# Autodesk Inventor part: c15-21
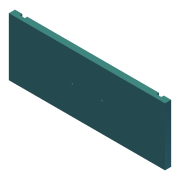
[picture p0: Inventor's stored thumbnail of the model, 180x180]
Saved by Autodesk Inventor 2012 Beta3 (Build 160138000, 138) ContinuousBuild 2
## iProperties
Created: 2011-02
Part Number: c15-21
Material: Default
Document SubType Name: Modeling
Designer: Beta-8540w
Density: 1 g/cm^3
Author: Beta-8540w
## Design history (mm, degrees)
sketch "Sketch1"
  geometry: L1 (-202.2, -75.2)-(202.2, -75.2); L2 (202.2, -75.2)-(202.2, 75.2); L3 (202.2, 75.2)-(-202.2, 75.2); L4 (-202.2, 75.2)-(-202.2, -75.2); 3 further points
  constraints: 8 end point, 2 midpoint, 2 parallel, 1 horizontal, 1 horizontal alignment, 1 perpendicular, 1 vertical alignment
  dimensions: "drawer_core_width" = 404.4 distance of L3.end L2.end (= drawer_width - 2 x edge_band_thickness); "drawer_core_height" = 150.4 distance of L2.end L1.end (= drawer_height - 2 x edge_band_thickness)
extrude "Drawer Face" new body sketch "Sketch1" distance "d2" = 15.875; taper "d3" = 0 deg
sketch "Sketch2"
  geometry: 1 further point
hole "Single Hole Pull" sketch "Sketch2" at (0, 0) diameter "d4" = 4.4958; stored, may be unused: countersink angle "d8" = 82 deg, drill point angle "d10" = 118 deg; dims "d5" = 19.05, "d6" = 8.4328, "d7" = 6.35, "d9" = 25.4
sketch "Sketch3"
  geometry: L1 (-38.1, 0)-(38.1, 0); 2 further points
  constraints: 2 end point, 1 coincident, 1 horizontal, 1 midpoint
  dimensions: "pull_width" = 76.2 distance of L1.start L1.end
hole "Double Hole Pull" sketch "Sketch3" at (-38.1, 0), (38.1, 0) diameter "d12" = 4.4958; stored, may be unused: countersink angle "d16" = 82 deg, drill point angle "d18" = 118 deg; dims "d13" = 19.05, "d14" = 8.4328, "d15" = 6.35, "d17" = 25.4
sketch "Sketch4"
  geometry: L1 (202.2, -75.2)-(-202.2, -75.2) reference; L2 (202.2, 75.2)-(202.2, -75.2) reference; L3 (-202.2, 75.2)-(202.2, 75.2) reference; L4 (-202.2, -75.2)-(-202.2, 75.2) reference; L5 (-183.15, 75.2)-(-170.45, 75.2); L6 (-170.45, 75.2)-(-170.45, -75.2); L7 (-170.45, -75.2)-(-183.15, -75.2); L8 (-183.15, -75.2)-(-183.15, 75.2); L9 (183.15, 75.2)-(170.45, 75.2); L10 (170.45, 75.2)-(170.45, -75.2); L11 (170.45, -75.2)-(183.15, -75.2); L12 (183.15, -75.2)-(183.15, 75.2); 1 further point
  constraints: 16 end point, 4 parallel, 4 point on line, 2 horizontal, 2 perpendicular, 1 collinear
  dimensions: "d19" = 12.7 distance of L5.start L5.end; "d20" = 19.05 distance between parallel lines of L8 L4; "d21" = 19.05 distance between parallel lines of L2 L12 (= d20)
extrude "Side Relief" cut sketch "Sketch4" distance "d22" = 6.35; taper "d23" = 0 deg
sketch "Sketch5"
  geometry: L1 (170.45, -75.2)-(170.45, 75.2) reference; L2 (-170.45, 75.2)-(-170.45, -75.2) reference; L3 (170.45, -75.2)-(-170.45, -75.2) reference; L4 (-170.45, -65.548)-(170.45, -65.548); L5 (170.45, -65.548)-(170.45, -62.246); L6 (170.45, -62.246)-(-170.45, -62.246); L7 (-170.45, -62.246)-(-170.45, -65.548); 1 further point
  constraints: 8 end point, 2 parallel, 2 point on line, 1 horizontal, 1 perpendicular
  dimensions: "d24" = 9.652 distance between parallel lines of L3 L4; "d25" = 3.302 distance of L4.end L5.end
extrude "Bottom Relief" cut sketch "Sketch5" distance "d26" = 6.35; taper "d27" = 0 deg
body "Solid1"
other parameters: "d28" = 0, "d29" = 0, "d30" = 0, "d31" = 0, "d32" = 0, "d33" = 180 deg, "d40" = 0, "d41" = 0, "d42" = 0, "d43" = 0, "d44" = 180 deg, "d45" = 180 deg, "d46" = 0, "d47" = 0, "d48" = 0, "d49" = 0, "d50" = 180 deg, "d51" = 0, "d52" = 0, "d53" = 0, "d54" = 0, "d55" = 0, "d56" = 180 deg, "d57" = 0, "drawer_width" = 406.4 [user parameter; used in 1 equation term], "edge_band_thickness" = 1 [user parameter; used in 2 equation terms], "drawer_height" = 152.4 [user parameter; used in 1 equation term]
